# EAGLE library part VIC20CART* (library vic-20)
VIC-20 cartridge port connector
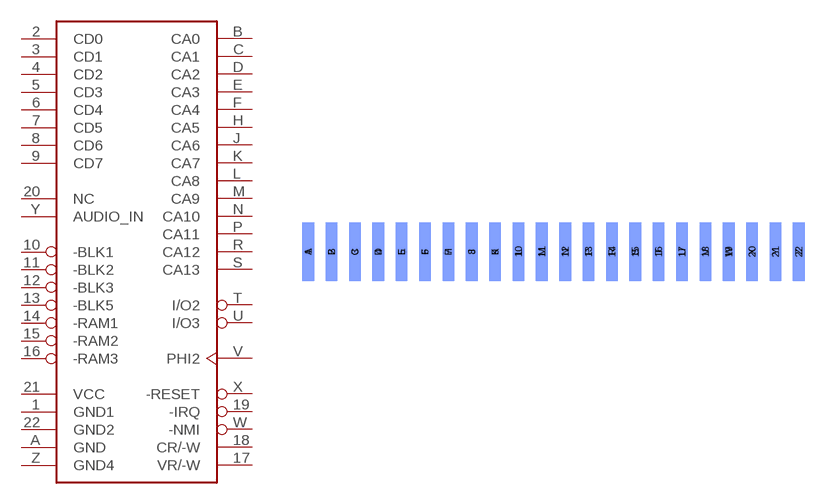
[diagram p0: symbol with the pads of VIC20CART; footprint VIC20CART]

Designator prefix -

## VIC20CART1  [VIC20CART]
1  GND1  pas
2  CD0
3  CD1
4  CD2
5  CD3
6  CD4
7  CD5
8  CD6
9  CD7
10  -BLK1  out
11  -BLK2  out
12  -BLK3  out
13  -BLK5  out
14  -RAM1  out
15  -RAM2  out
16  -RAM3  out
17  VR/-W  out
18  CR/-W  out
19  -IRQ  out
20  NC  nc
21  VCC  pwr
22  GND2  pas
A  GND  pas
B  CA0  out
C  CA1  out
D  CA2  out
E  CA3  out
F  CA4  out
H  CA5  out
J  CA6  out
K  CA7  out
L  CA8  out
M  CA9  out
N  CA10  out
P  CA11  out
R  CA12  out
S  CA13  out
T  I/O2  out
U  I/O3  out
V  PHI2  out
W  -NMI  out
X  -RESET  out
Y  AUDIO_IN  in
Z  GND4  pas

## Footprint VIC20CART (pad centres in mm)
VIC-20 cartridge port connector
smd 1.98 x 9.9: 1 -41.58,0; 2 -37.62,0; 3 -33.66,0; 4 -29.7,0; 5 -25.74,0; 6 -21.78,0; 7 -17.82,0; 8 -13.86,0; 9 -9.9,0; 10 -5.94,0; 11 -1.98,0; 12 1.98,0; 13 5.94,0; 14 9.9,0; 15 13.86,0; 16 17.82,0; 17 21.78,0; 18 25.74,0; 19 29.7,0; 20 33.66,0; 21 37.62,0; 22 41.58,0
smd 1.98 x 9.9 bottom: A -41.58,0; B -37.62,0; C -33.66,0; D -29.7,0; E -25.74,0; F -21.78,0; H -17.82,0; J -13.86,0; K -9.9,0; L -5.94,0; M -1.98,0; N 1.98,0; P 5.94,0; R 9.9,0; S 13.86,0; T 17.82,0; U 21.78,0; V 25.74,0; W 29.7,0; X 33.66,0; Y 37.62,0; Z 41.58,0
